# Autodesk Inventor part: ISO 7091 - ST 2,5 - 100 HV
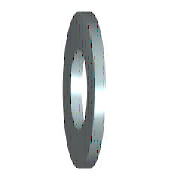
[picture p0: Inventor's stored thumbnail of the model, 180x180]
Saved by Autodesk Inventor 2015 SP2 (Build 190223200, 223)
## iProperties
Created: 2012-02
Part Number: ISO 7091 - ST 2,5 - 100 HV
Material: Stahl
Description: Unterlegscheiben - normale Ausführung - Produktklasse C
Document SubType Name: Modeling
Standard: ISO 7091
Designer: Hübner
Standard Revision: Second edition 2000-06-01
Standards Organization: ISO
Language: de-DE
Size Designation: ST 2,5 - 100 HV
Categories: <MemberInstance><Categories><Category DisplayName="Verbindungselemente" InternalName="e4da775c-781d-43d5-af7c-5136215cf5a6" Mnemonic="FSTN"><Category DisplayNam
Density: 7.85 g/cm^3
Appearance: Platte
IsCustomPart: 0
Author: Hübner
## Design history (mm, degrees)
sketch "Skizze"
  geometry: C1 r 3 at (0, 0); C2 r 1.45 at (0, 0); 1 further point
  constraints: 2 centre point, 2 coincident
  dimensions: "d0" = 2.9 diameter of C2 (= SD1); "d1" = 6 diameter of C1 (= SD2)
extrude "Körper" new body sketch "Skizze" distance "d2" = 0.5 (= SD); taper "d3" = 0 deg
workaxis "Work Axis1"
workplane "Work Plane1"
body "Solid1"
other parameters: "SD1" = 2.9 [user parameter; used in 1 equation term], "SD2" = 6 [user parameter; used in 1 equation term], "SD" = 0.5 [user parameter; used in 1 equation term], "d4" = 0, "d5" = 0, "d6" = 0, "d7" = 0, "NND" = 2.5 [user parameter]
